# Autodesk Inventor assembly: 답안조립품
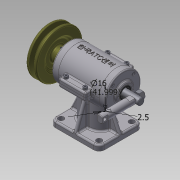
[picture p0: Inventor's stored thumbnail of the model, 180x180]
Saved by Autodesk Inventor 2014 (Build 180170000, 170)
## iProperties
Created: 2015-05
Part Number: 답안조립품
Document SubType Name: Assembly
Designer: Administrator
Author: Administrator
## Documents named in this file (18)
- C:\Documents and Settings\Administrator\바탕 화면\350508V1042\답안조립품.iam
- C:\Documents and Settings\Administrator\바탕 화면\350508V1042\가변스프링.ipt
- C:\Documents and Settings\Administrator\바탕 화면\350508V1042\본체.ipt
- C:\Documents and Settings\Administrator\바탕 화면\350508V1042\본체 커버.ipt
- C:\Documents and Settings\Administrator\바탕 화면\350508V1042\앞커버.ipt
- C:\Documents and Settings\Administrator\바탕 화면\350508V1042\뒤커버.ipt
- C:\Documents and Settings\Administrator\바탕 화면\350508V1042\M4x0.5x14.ipt
- C:\Documents and Settings\Administrator\바탕 화면\350508V1042\M3x0.5x8.ipt
- C:\Documents and Settings\Administrator\바탕 화면\350508V1042\편심축.ipt
- C:\Documents and Settings\Administrator\바탕 화면\350508V1042\베어링 6201.ipt
- C:\Documents and Settings\Administrator\바탕 화면\350508V1042\오일실.ipt
- C:\Documents and Settings\Administrator\바탕 화면\350508V1042\V-벨트풀리.ipt
- C:\Documents and Settings\Administrator\바탕 화면\350508V1042\키4x4.ipt
- C:\Documents and Settings\Administrator\바탕 화면\350508V1042\멈춤나사.ipt
- C:\Documents and Settings\Administrator\바탕 화면\350508V1042\베어링 6202.ipt
- C:\Documents and Settings\Administrator\바탕 화면\350508V1042\링크.ipt
- C:\Documents and Settings\Administrator\바탕 화면\350508V1042\너트 M8.ipt
- C:\Documents and Settings\Administrator\바탕 화면\350508V1042\슬라이드.ipt
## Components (15 placed, 5 different names)
1. 가변스프링:1
2. M4x0.5x14:1
3. M4x0.5x14:2
4. M4x0.5x14:3
5. M4x0.5x14:4
6. V-벨트풀리:1 — 플러쉬:1
7. KS B 1012 C - 미터 C M8:1
8. M3x0.5x8:1
9. M3x0.5x8:6
10. M3x0.5x8:7
11. M3x0.5x8:8
12. M3x0.5x8:9
13. M3x0.5x8:10
14. M3x0.5x8:11
15. M3x0.5x8:12
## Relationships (1: Flush 1)
- 플러쉬:1 [Flush]: V-벨트풀리:1
